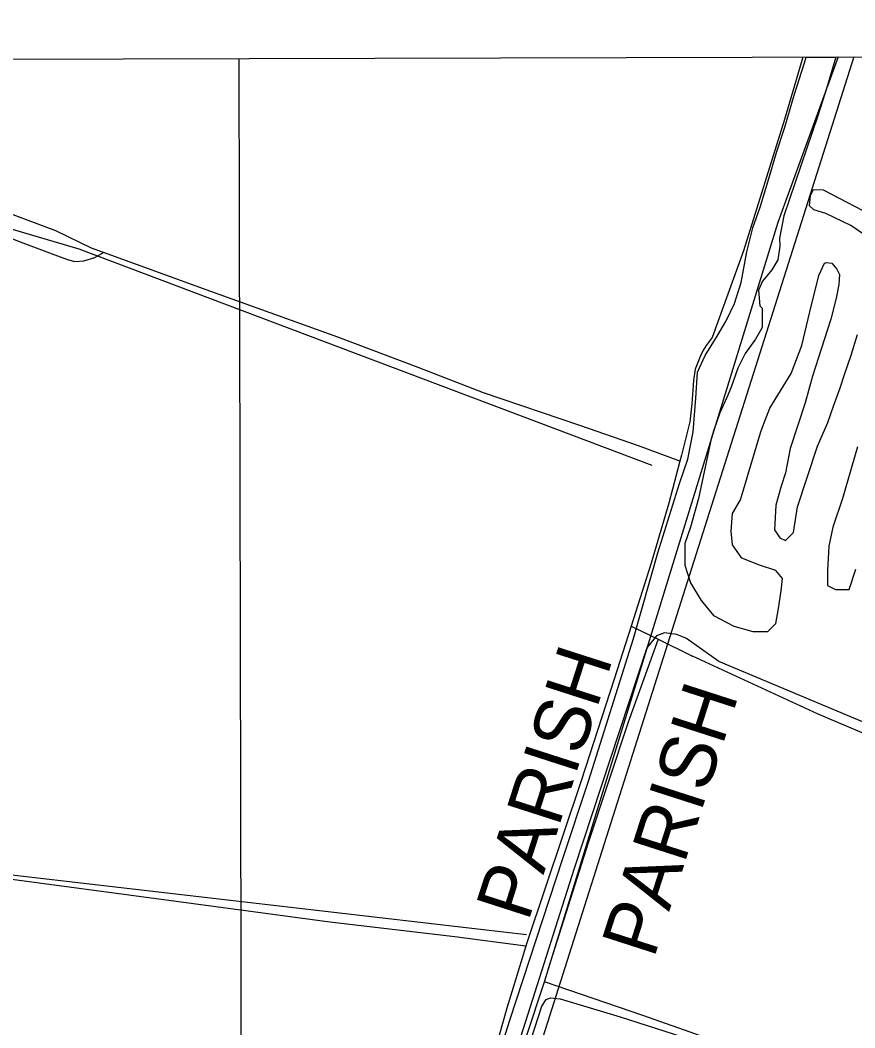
# Model space of a CAD drawing. Extents: x 3355724 to 3393621, y 594744 to 620174.
# Drawn here: x 3364679 to 3366177, y 616587 to 618395 of the extents above; entities that cross this region are included whole.
import ezdxf

# ---------------------------------------------------------------- set-up
doc = ezdxf.new("R2010")
doc.units = 0
for name, color, linetype in [('V-DTCH-CNTR', 7, 'Continuous'), ('V-GRID-FRAM', 7, 'Continuous'), ('V-GRID-MAJR', 7, 'Continuous'), ('V-SITE-VEGE', 7, 'Continuous'), ('V-TOPO-BNDY', 7, 'Continuous'), ('V-TOPO-GNAM-IDEN', 7, 'Continuous'), ('V-TOPO-SHOR', 7, 'Continuous')]:
    doc.layers.add(name, color=color, linetype=linetype)

msp = doc.modelspace()

# ---------------------------------------------------------------- linework, layer by layer
at = {"layer": 'V-DTCH-CNTR'}
for points in [[(3366084.2235411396, 618328.5005824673), (3366050.768, 618216.676), (3365977.4050000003, 617980.988), (3365921.125, 617825.457)], [(3365863.47, 617603.743), (3365788.8140000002, 617631.372), (3365684.024, 617667.843), (3365510.9930000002, 617726.557), (3365393.421, 617771.435), (3365249.637, 617826.022), (3365021.744, 617908.045), (3364828.6750000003, 617977.8960000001), (3364807.339, 617985.617), (3364743.648, 618016.6240000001), (3364594.318, 618072.6730000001), (3364413.955, 618143.061), (3364309.823, 618185.85), (3364222.449, 618218.737), (3364142.196, 618250.194), (3363976.185, 618316.922)], [(3363966.545, 618252.867), (3364063.245, 618226.476), (3364194.295, 618177.934), (3364246.761, 618156.154), (3364309.47, 618134.582), (3364410.306, 618098.8200000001), (3364559.603, 618044.3470000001), (3364679.589, 617997.153), (3364751.079, 617970.247), (3364766.16, 617965.039), (3364777.254, 617962.112), (3364793.7830000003, 617963.241), (3364813.366, 617969.159), (3364828.6750000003, 617977.8960000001)], [(3365921.125, 617825.457), (3365910.3880000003, 617811.05), (3365904.279, 617801.465), (3365900.5160000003, 617792.718), (3365890.7600000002, 617768.873), (3365888.0300000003, 617748.323), (3365884.948, 617706.487), (3365880.882, 617674.087), (3365866.339, 617614.675), (3365863.47, 617603.743), (3365843.678, 617528.297), (3365812, 617420.453), (3365775.691, 617307.784), (3365824.38, 617284.142), (3365886.137, 617254.155)], [(3365775.691, 617307.784), (3365745.329, 617212.579), (3365686.021, 617030.077), (3365588.731, 616739.604), (3365586.855, 616733.525), (3365552.518, 616622.206), (3365518.734, 616501.71), (3365477.893, 616379.4890000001), (3365409.502, 616178.675), (3365370.22, 616057.273), (3365336.292, 615943.867), (3365237.472, 615637.046)], [(3365824.38, 617284.142), (3365770.677, 617135.65), (3365698.67, 616918.9940000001), (3365626.857, 616692.887)], [(3366706.685, 616915.908), (3366629.576, 616942.802), (3366487.856, 616993.15), (3366338.477, 617053.892), (3366111.276, 617149.857), (3365886.137, 617254.155)], [(3365586.855, 616733.525), (3365459.607, 616750.62), (3365235.224, 616776.752), (3364959.389, 616813.6510000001), (3364628.225, 616858.086), (3364621.9050000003, 616858.746), (3364610.137, 616856.139), (3364596.02, 616852.696), (3364547.864, 616856.438), (3364362.2, 616877.848), (3364089.595, 616910.8740000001), (3363814.612, 616944.639), (3363783.839, 616946.372), (3363772.8880000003, 616942.206), (3363768.292, 616935.806), (3363759.5500000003, 616900.947), (3363742.91, 616751.638), (3363712.904, 616485.402), (3363682.5670000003, 616197.088), (3363677.417, 616157.005), (3363649.267, 615937.879), (3363638.242, 615825.2880000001)], [(3365404.298, 615981.5750000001), (3365492.686, 616245.069), (3365577.903, 616509.285), (3365615.705, 616625.925), (3365623.342, 616637.906), (3365631.1550000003, 616641.218), (3365648.539, 616639.211), (3365756.399, 616606.7440000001), (3365899.863, 616561.129)]]:
    msp.add_lwpolyline(points, dxfattribs=at)
at = {"layer": 'V-GRID-FRAM'}
msp.add_lwpolyline([(3359807.561, 618312.068), (3391397.168, 618394.7710000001), (3391452.708, 600211.218), (3359847.233, 600128.473), (3359807.561, 618312.068)], dxfattribs=at)
at = {"layer": 'V-GRID-MAJR'}
msp.add_spline([(3365114.812, 600142.264), (3365100.711, 606201.524), (3365086.606, 612262.72), (3365072.5, 618323.938), (3365072.4960000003, 618325.852)], degree=3, dxfattribs=at)
at = {"layer": 'V-SITE-VEGE'}
for p, q in [((3366086.774, 618318.1900000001), (3366090.092626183, 618328.515947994)), ((3366090.092626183, 618328.515947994), (3366143.146462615, 618328.654845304)), ((3366143.146462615, 618328.654845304), (3366126.917, 618274.094)), ((3366068.2660000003, 618260.155), (3366086.774, 618318.1900000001)), ((3366126.917, 618274.094), (3366111.1550000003, 618222.974)), ((3366051.829, 618202.816), (3366068.2660000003, 618260.155)), ((3366111.1550000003, 618222.974), (3366050.1210000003, 618044.0260000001)), ((3366036.7430000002, 618157.2169999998), (3366051.829, 618202.816)), ((3366023.73, 618112.312), (3366036.7430000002, 618157.2169999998)), ((3366007.2830000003, 618059.116), (3366023.73, 618112.312)), ((3365994.2490000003, 618022.495), (3366007.2830000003, 618059.116)), ((3366050.1210000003, 618044.0260000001), (3366041.929, 618003.965)), ((3365983.303, 617978.9749999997), (3365994.2490000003, 618022.495)), ((3366041.929, 618003.965), (3366042.6520000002, 617989.4669999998)), ((3365973.073, 617924.4119999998), (3365983.303, 617978.9749999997)), ((3366042.6520000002, 617989.4669999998), (3366039.256, 617964.607)), ((3366039.256, 617964.607), (3366028.25, 617946.631)), ((3366112.501, 617936.469), (3366122.806, 617958.583)), ((3366122.806, 617958.583), (3366126.255, 617959.974)), ((3366126.255, 617959.974), (3366135.924, 617958.6140000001)), ((3366135.924, 617958.6140000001), (3366144.923, 617948.28)), ((3366028.25, 617946.631), (3366011.7290000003, 617926.5709999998)), ((3366144.923, 617948.28), (3366149.776, 617938.626)), ((3365961.4220000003, 617886.416), (3365973.073, 617924.4119999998)), ((3366011.7290000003, 617926.5709999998), (3366004.17, 617910.677)), ((3366096.77, 617871.537), (3366112.501, 617936.469)), ((3366149.776, 617938.626), (3366148.4390000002, 617920.6730000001)), ((3366004.17, 617910.677), (3366006.9960000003, 617882.377)), ((3366148.4390000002, 617920.6730000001), (3366143.661, 617895.806)), ((3365946.306, 617855.313), (3365961.4220000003, 617886.416)), ((3366143.661, 617895.806), (3366134.0810000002, 617858.506)), ((3366006.9960000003, 617882.377), (3366011.147, 617878.2439999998)), ((3366011.147, 617878.2439999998), (3366011.227, 617843.7269999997)), ((3366082.412, 617811.441), (3366096.77, 617871.537)), ((3365930.491, 617827.6630000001), (3365946.306, 617855.313)), ((3366134.0810000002, 617858.506), (3366122.43, 617821.197)), ((3366011.227, 617843.7269999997), (3365998.849, 617822.295)), ((3365908.477, 617793.093), (3365930.491, 617827.6630000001)), ((3365998.849, 617822.295), (3365980.268, 617796.709)), ((3366122.43, 617821.197), (3366112.144, 617789.417)), ((3366170.8200000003, 617793.693), (3366181.781, 617830.9990000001)), ((3365980.268, 617796.709), (3365967.2120000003, 617770.446)), ((3366063.1950000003, 617760.998), (3366082.412, 617811.441)), ((3365894.737, 617763.3740000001), (3365908.477, 617793.093)), ((3366112.144, 617789.417), (3366101.177, 617756.253)), ((3366158.472, 617759.145), (3366170.8200000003, 617793.693)), ((3365891.935, 617716.973), (3365894.737, 617763.3740000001)), ((3365967.2120000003, 617770.446), (3365955.552, 617736.588)), ((3366024.676, 617698.7760000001), (3366063.1950000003, 617760.9979999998)), ((3366150.934, 617734.964), (3366158.472, 617759.145)), ((3366101.177, 617756.253), (3366088.169, 617708.586)), ((3365955.552, 617736.588), (3365947.309, 617717.929)), ((3366139.27, 617702.491), (3366150.934, 617734.964)), ((3365887.0670000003, 617656.061), (3365891.935, 617716.973)), ((3365947.309, 617717.929), (3365934.947, 617690.287)), ((3366088.169, 617708.586), (3366061.432, 617626.371)), ((3365934.947, 617690.287), (3365923.972, 617659.1939999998)), ((3366011.637, 617664.919), (3366024.676, 617698.7760000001)), ((3366128.983, 617672.7809999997), (3366139.27, 617702.491)), ((3366110.441, 617630.625), (3366128.983, 617672.7809999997)), ((3365877.329, 617607.331), (3365887.0670000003, 617656.061)), ((3365923.972, 617659.1939999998), (3365919.174, 617643.9940000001)), ((3365972.276, 617534.242), (3366008.208, 617654.556)), ((3366008.208, 617654.556), (3366011.637, 617664.919)), ((3365919.174, 617643.9940000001), (3365896.803, 617536.679)), ((3366061.432, 617626.371), (3366052.617, 617582.9720000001)), ((3366074.531, 617522.06), (3366110.441, 617630.625)), ((3366182.241, 617629.408), (3366154.872, 617536.679)), ((3365862.721, 617563.475), (3365877.329, 617607.331)), ((3366052.617, 617582.9720000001), (3366045.3140000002, 617558.607)), ((3365823.768, 617439.215), (3365862.721, 617563.475)), ((3366045.3140000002, 617558.607), (3366035.576, 617524.497)), ((3365896.803, 617536.679), (3365882.1950000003, 617485.514)), ((3365957.67, 617509.879), (3365972.276, 617534.242)), ((3366035.576, 617524.497), (3366033.1410000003, 617480.64)), ((3366154.872, 617536.679), (3366137.8310000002, 617485.514)), ((3365955.235, 617478.202), (3365957.67, 617509.879)), ((3366067.2260000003, 617475.767), (3366074.531, 617522.06)), ((3365882.1950000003, 617485.514), (3365872.457, 617456.274)), ((3365957.67, 617453.839), (3365955.235, 617478.202)), ((3366033.1410000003, 617480.64), (3366042.879, 617466.0210000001)), ((3366052.617, 617461.149), (3366067.2260000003, 617475.767)), ((3366137.8310000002, 617485.514), (3366130.525, 617451.402)), ((3365872.457, 617456.274), (3365872.457, 617417.2930000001)), ((3365974.711, 617429.4739999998), (3365957.67, 617453.839)), ((3366042.879, 617466.0210000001), (3366052.617, 617461.149)), ((3365779.947, 617285.715), (3365823.768, 617439.215)), ((3366130.525, 617451.402), (3366128.09, 617407.546)), ((3365872.457, 617417.2930000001), (3365882.1950000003, 617385.616)), ((3366006.361, 617417.2930000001), (3365974.711, 617429.4739999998)), ((3366035.576, 617407.546), (3366006.361, 617417.2930000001)), ((3366047.7490000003, 617392.93), (3366035.576, 617407.546)), ((3366128.09, 617407.546), (3366128.09, 617380.7440000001)), ((3366167.0470000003, 617373.435), (3366179.219, 617409.981)), ((3365882.1950000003, 617385.616), (3365901.6720000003, 617353.9419999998)), ((3366045.3140000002, 617370.998), (3366047.7490000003, 617392.93)), ((3366128.09, 617380.7440000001), (3366142.699, 617373.435)), ((3366040.444, 617339.3229999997), (3366045.3140000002, 617370.998)), ((3366142.699, 617373.435), (3366167.0470000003, 617373.435)), ((3365901.6720000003, 617353.9419999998), (3365923.583, 617327.142)), ((3365923.583, 617327.142), (3365960.103, 617307.649)), ((3366035.576, 617312.523), (3366040.444, 617339.3229999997)), ((3365960.103, 617307.649), (3365994.188, 617297.905)), ((3366020.968, 617297.905), (3366035.576, 617312.523)), ((3365821.3310000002, 617290.591), (3365804.287, 617268.6630000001)), ((3365835.9390000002, 617295.466), (3365821.3310000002, 617290.591)), ((3365857.848, 617293.03), (3365835.9390000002, 617295.4659999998)), ((3365874.892, 617285.719), (3365857.848, 617293.03)), ((3365994.188, 617297.905), (3366020.968, 617297.905)), ((3365699.602, 617029.885), (3365779.947, 617285.715)), ((3365933.321, 617244.2980000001), (3365874.892, 617285.719)), ((3365804.287, 617268.6630000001), (3365672.8200000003, 616871.517)), ((3366193.827, 617134.659), (3365933.321, 617244.2980000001)), ((3365653.343, 616891.006), (3365699.602, 617029.885)), ((3365558.396, 616601.0669999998), (3365653.343, 616891.006)), ((3365672.8200000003, 616871.517), (3365344.149, 615836.014)), ((3365482.921, 616362.29), (3365558.396, 616601.0669999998))]:
    msp.add_line(p, q, dxfattribs=at)
msp.add_lwpolyline([(3366120.568, 618090.13), (3366218.899, 618039.203), (3366229.159, 618025.586), (3366227.813, 618018.08), (3366221.7, 618006.4720000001), (3366214.205, 618003.725), (3366200.559, 618005.743), (3366169.818, 618026.13), (3366125.438, 618047.856), (3366103.596, 618054.626), (3366096.08, 618061.43), (3366097.401, 618080.529), (3366102.832, 618090.772)], close=True, dxfattribs=at)
at = {"layer": 'V-TOPO-BNDY'}
msp.add_line((3366175.3726456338, 618328.7392148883), (3364077.6720000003, 611719.626), dxfattribs=at)
at = {"layer": 'V-TOPO-SHOR'}
for p, q in [((3364784.387, 617984.742), (3365813.1834176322, 617596.4101982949)), ((3364582.022, 616870.991), (3365587.790766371, 616754.7035825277))]:
    msp.add_line(p, q, dxfattribs=at)
for points in [[(3363805.548, 610367.725), (3363988.463836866, 611545.4894988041), (3364076.4863758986, 611941.5394890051), (3364262.9190929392, 612545.6523793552), (3364459.143605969, 613189.3728593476), (3365283.9083098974, 615655.508774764), (3365620.102, 616669.652), (3366039.6382237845, 618032.4045589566), (3366147.7106666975, 618329.552153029)], [(3363982.747, 618289.589), (3364132.7830000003, 618231.2440000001), (3364330.454, 618154.188), (3364489.936, 618096.037), (3364664.747, 618020.087), (3364784.387, 617984.742)], [(3365901.909, 616572.184), (3365797.105, 616609.443), (3365620.102, 616669.652)]]:
    msp.add_lwpolyline(points, dxfattribs=at)

# ---------------------------------------------------------------- texts
at = {"layer": 'V-TOPO-GNAM-IDEN'}
for p in [(3365591.0445172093, 616775.801948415), (3365816.5213625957, 616709.8251282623)]:
    msp.add_text('PARISH', height=99.99980199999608, rotation=72.16035010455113, dxfattribs=at).set_placement(p)

doc.saveas('drawing.dxf')
